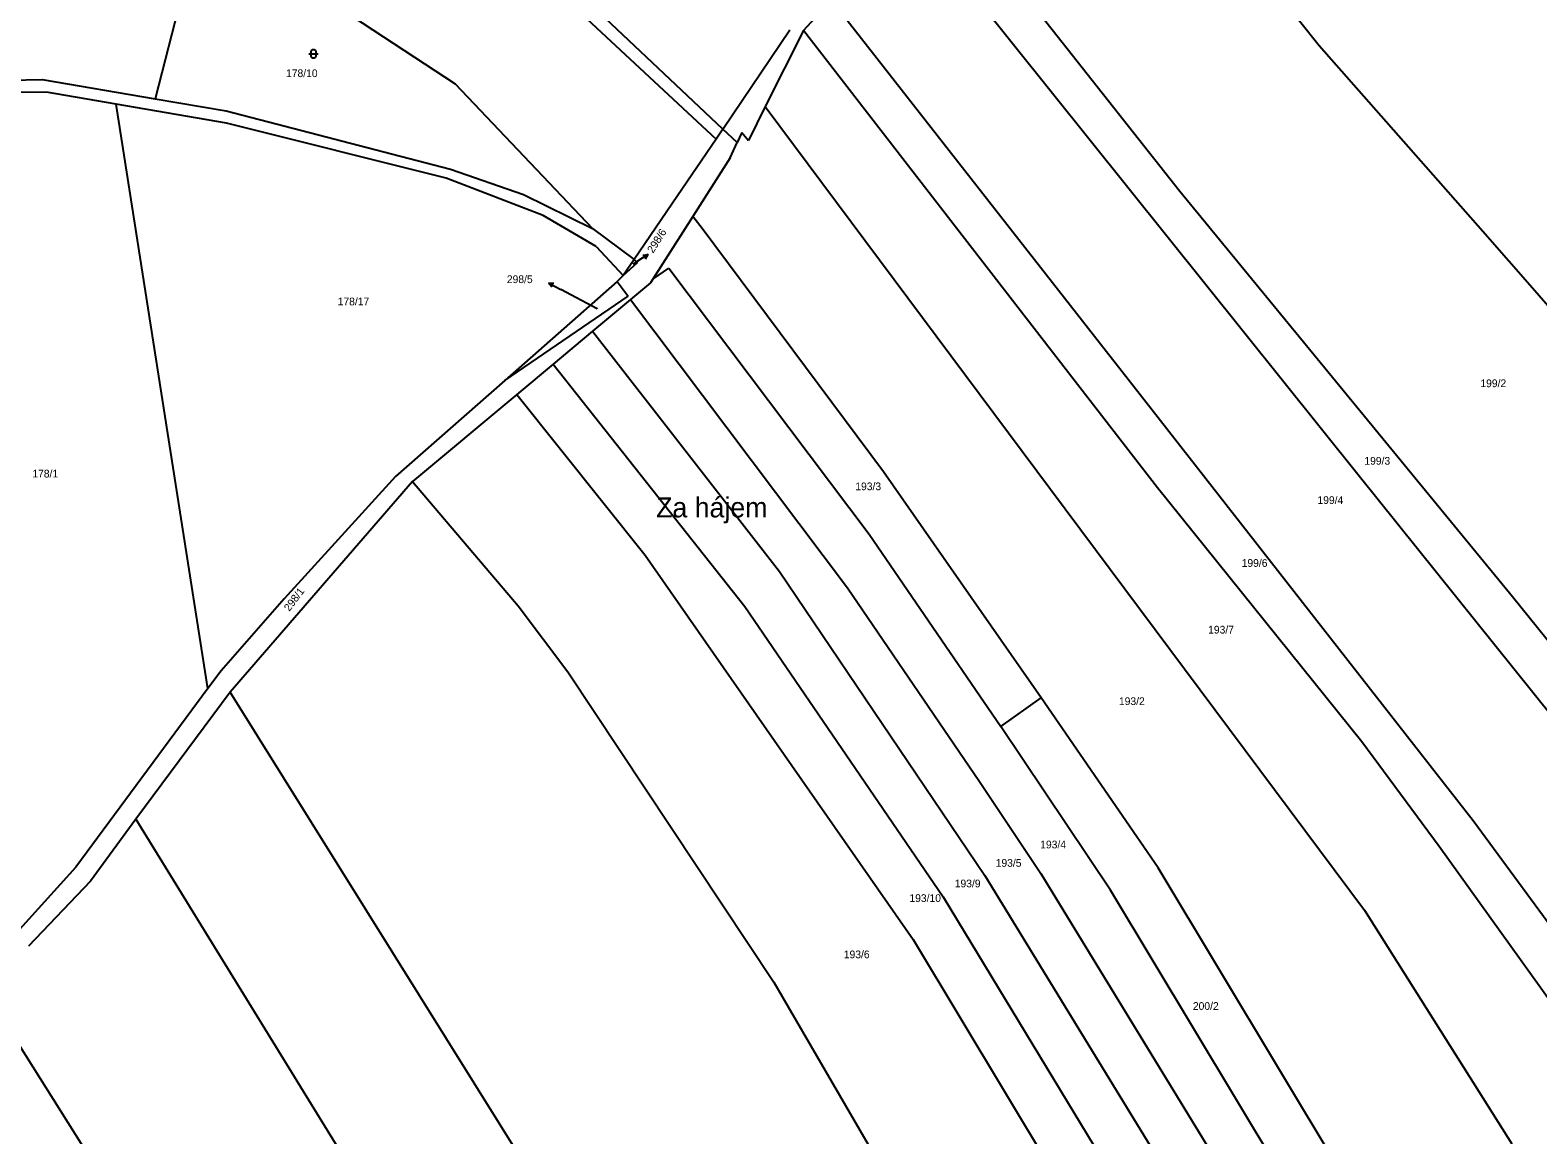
# Model space of a CAD drawing. Extents: x -779723 to -777378, y -1011169 to -1009297.
# Drawn here: x -779291.4 to -778959.2, y -1010989 to -1010745.7 of the extents above; entities that cross this region are included whole.
import ezdxf

# ---------------------------------------------------------------- set-up
doc = ezdxf.new("R2010")
doc.units = 0
for name, color, linetype in [('Default', 7, 'Continuous'), ('KN_HRANICE', 7, 'Continuous'), ('KN_KULTURY', 7, 'Continuous'), ('KN_PARCELY', 7, 'Continuous')]:
    doc.layers.add(name, color=color, linetype=linetype)

# ---------------------------------------------------------------- blocks, each defined once
blk = doc.blocks.new('316')
at = {"layer": 'Default'}
for points in [[(-1, 1), (0.27, 1), (1, 1)], [(-0.5, 1.5), (-0.4, 1.79), (-0.15, 1.97), (0.16, 1.97), (0.41, 1.79), (0.51, 1.5), (0.51, 0.5), (0.41, 0.21), (0.16, 0.03), (-0.15, 0.03), (-0.4, 0.21), (-0.5, 0.5), (-0.5, 1.5)]]:
    blk.add_lwpolyline(points, dxfattribs=at)
blk = doc.blocks.new('10292')
at = {"layer": 'Default'}
blk.add_line((0, 3), (0, 0), dxfattribs=at)
blk.add_lwpolyline([(-0.5, 2), (0, 3), (0.5, 2)], dxfattribs=at)

msp = doc.modelspace()

# ---------------------------------------------------------------- linework, layer by layer
at = {"layer": 'KN_HRANICE'}
for p, q in [((-779090.15, -1010715.21), (-779038.14, -1010781.12)), ((-779034.27, -1010715.3), (-779007.39, -1010749.08)), ((-778998.61, -1010843.93), (-779096.96, -1010721.21)), ((-779246.07, -1010725.76), (-779197.77, -1010757.47)), ((-779255.21, -1010727.12), (-779263.87, -1010760.8)), ((-779138.78, -1010767.46), (-779171.89, -1010736.2)), ((-779174.03, -1010738.22), (-779140.28, -1010769.67)), ((-779121, -1010745.73), (-779114.85, -1010739.08)), ((-779114.85, -1010739.08), (-779044.24, -1010829.34)), ((-779138.78, -1010767.46), (-779124.03, -1010745.63)), ((-779121, -1010745.73), (-779129.44, -1010762.47)), ((-779043.05, -1010846.46), (-779121, -1010745.73)), ((-779007.39, -1010749.08), (-778971.37, -1010789.97)), ((-779295.87, -1010756.68), (-779288.73, -1010756.56)), ((-779287.82, -1010759.31), (-779295.7, -1010759.39)), ((-779288.73, -1010756.56), (-779263.87, -1010760.8)), ((-779272.43, -1010762.01), (-779287.82, -1010759.31)), ((-779197.77, -1010757.47), (-779167.5, -1010789.36)), ((-779252.21, -1010890.71), (-779272.43, -1010762.01)), ((-779248.15, -1010766.16), (-779272.43, -1010762.01)), ((-779263.87, -1010760.8), (-779248.18, -1010763.48)), ((-779129.44, -1010762.47), (-779133.14, -1010770)), ((-779129.44, -1010762.47), (-779063.39, -1010851.12)), ((-779248.18, -1010763.48), (-779198.78, -1010776.27)), ((-779199.71, -1010778.27), (-779248.15, -1010766.16)), ((-779138.78, -1010767.46), (-779140.28, -1010769.67)), ((-779135.61, -1010770.46), (-779138.78, -1010767.46)), ((-779134.58, -1010768.25), (-779135.61, -1010770.46)), ((-779134.58, -1010768.25), (-779133.14, -1010770)), ((-779140.28, -1010769.67), (-779148.79, -1010782.17)), ((-779137.14, -1010773.83), (-779135.61, -1010770.46)), ((-779137.14, -1010773.83), (-779143.83, -1010784.29)), ((-779178.37, -1010786.48), (-779199.71, -1010778.27)), ((-779198.78, -1010776.27), (-779182.71, -1010781.86)), ((-779182.71, -1010781.86), (-779167.5, -1010789.36)), ((-779148.79, -1010782.17), (-779158.36, -1010796.23)), ((-779038.14, -1010781.12), (-778964.83, -1010870.44)), ((-779143.83, -1010784.29), (-779145.37, -1010786.69)), ((-779166.68, -1010793.33), (-779178.37, -1010786.48)), ((-779167.5, -1010789.36), (-779158.36, -1010796.23)), ((-779145.37, -1010786.69), (-779154.19, -1010800.5)), ((-779143.35, -1010789.4), (-779145.37, -1010786.69)), ((-779103.43, -1010842.99), (-779143.35, -1010789.4)), ((-778971.37, -1010789.97), (-778959.93, -1010803)), ((-779166.68, -1010793.33), (-779160.74, -1010799.73)), ((-779158.36, -1010796.23), (-779160.74, -1010799.73)), ((-779160.74, -1010799.73), (-779157.56, -1010796.83)), ((-779158.36, -1010796.23), (-779157.56, -1010796.83)), ((-779154.19, -1010800.5), (-779150.71, -1010798.11)), ((-779150.71, -1010798.11), (-779106.53, -1010856.72)), ((-779162.08, -1010801.02), (-779186.85, -1010822.84)), ((-779162.08, -1010801.02), (-779160.74, -1010799.73)), ((-779162.08, -1010801.02), (-779159.66, -1010804.24)), ((-779154.73, -1010801.34), (-779159.1, -1010804.99)), ((-779154.19, -1010800.5), (-779154.73, -1010801.34)), ((-779186.85, -1010822.84), (-779159.66, -1010804.24)), ((-779159.1, -1010804.99), (-779167.52, -1010812.01)), ((-779159.1, -1010804.99), (-779111.3, -1010868.53)), ((-778959.93, -1010803), (-778909.95, -1010860.69)), ((-779167.52, -1010812.01), (-779176.17, -1010819.22)), ((-779167.52, -1010812.01), (-779126.3, -1010864.94)), ((-779176.17, -1010819.22), (-779184.17, -1010825.9)), ((-779176.17, -1010819.22), (-779133.97, -1010872.59)), ((-779186.85, -1010822.84), (-779210.91, -1010844.02)), ((-779184.17, -1010825.9), (-779207.15, -1010845.06)), ((-779184.17, -1010825.9), (-779155.93, -1010861.31)), ((-779044.24, -1010829.34), (-778973.49, -1010919.73)), ((-779207.15, -1010845.06), (-779247.3, -1010891.46)), ((-779210.91, -1010844.02), (-779235.44, -1010870.94)), ((-779207.15, -1010845.06), (-779183.86, -1010872.45)), ((-779068.64, -1010892.72), (-779103.43, -1010842.99)), ((-778900.11, -1010966.64), (-778998.61, -1010843.93)), ((-778998.02, -1010902.45), (-779043.05, -1010846.46)), ((-779063.39, -1010851.12), (-778997.44, -1010939.52)), ((-779106.53, -1010856.72), (-779077.58, -1010899.08)), ((-779155.93, -1010861.31), (-779096.86, -1010945.95)), ((-779126.3, -1010864.94), (-779081.05, -1010931.89)), ((-779111.3, -1010868.53), (-779082.24, -1010911.14)), ((-779235.44, -1010870.94), (-779249.3, -1010886.77)), ((-778964.83, -1010870.44), (-778892.41, -1010960.42)), ((-779183.86, -1010872.45), (-779172.91, -1010886.98)), ((-779133.97, -1010872.59), (-779090.28, -1010936.59)), ((-779249.3, -1010886.77), (-779252.21, -1010890.71)), ((-779172.91, -1010886.98), (-779127.56, -1010955.39)), ((-779252.21, -1010890.71), (-779281.31, -1010930.07)), ((-779247.3, -1010891.46), (-779268.1, -1010919.48)), ((-779161.56, -1011028.82), (-779247.3, -1010891.46)), ((-779077.58, -1010899.08), (-779068.64, -1010892.72)), ((-779042.92, -1010930.15), (-779068.64, -1010892.72)), ((-779053.4, -1010935.08), (-779077.58, -1010899.08)), ((-778980.97, -1010925.46), (-778998.02, -1010902.45)), ((-779082.24, -1010911.14), (-779068.7, -1010931.41)), ((-779268.1, -1010919.48), (-779278.06, -1010933.1)), ((-779268.1, -1010919.48), (-779212.73, -1011009.48)), ((-778973.49, -1010919.73), (-778924.2, -1010986.99)), ((-778944.73, -1010976.05), (-778980.97, -1010925.46)), ((-779281.31, -1010930.07), (-779295.1, -1010945.28)), ((-779081.05, -1010931.89), (-779020.18, -1011031.25)), ((-779068.7, -1010931.41), (-779011.43, -1011025.21)), ((-778993.64, -1011012.17), (-779042.92, -1010930.15)), ((-779278.06, -1010933.1), (-779291.76, -1010947.43)), ((-779002.79, -1011019.26), (-779053.4, -1010935.08)), ((-779090.28, -1010936.59), (-779029.06, -1011037.37)), ((-778997.44, -1010939.52), (-778964.98, -1010991)), ((-779096.86, -1010945.95), (-779038.09, -1011043.59)), ((-779127.56, -1010955.39), (-779091.73, -1011017)), ((-779300.33, -1010958.9), (-779206.63, -1011107.76))]:
    msp.add_line(p, q, dxfattribs=at)
at = {"layer": 'KN_PARCELY'}
for p, q in [((-779158.56, -1010797.19), (-779157.83, -1010796.73)), ((-779166.51, -1010807.07), (-779174.48, -1010802.81))]:
    msp.add_line(p, q, dxfattribs=at)

# ---------------------------------------------------------------- block references
at = {"layer": 'KN_KULTURY'}
msp.add_blockref('316', (-779228.96, -1010751.91), dxfattribs=at)
at = {"layer": 'KN_PARCELY'}
for p, rotation in [((-779157.83, -1010796.73), -57.70746700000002), ((-779174.48, -1010802.81), 61.822146)]:
    msp.add_blockref('10292', p, dxfattribs=dict(at, rotation=rotation))

# ---------------------------------------------------------------- texts
for s, height, p in [('178/10', 1.7, (-779235.02, -1010756.02)), ('298/5', 1.7, (-779186.37, -1010801.39)), ('178/17', 1.7, (-779223.64, -1010806.29)), ('298/5', 0.1, (-779166.5, -1010807.07)), ('199/2', 1.7, (-778971.9, -1010824.31)), ('178/1', 1.7, (-779290.91, -1010844.21)), ('199/3', 1.7, (-778997.46, -1010841.39)), ('193/3', 1.7, (-779109.61, -1010847.01)), ('Za hájem', 4.4, (-779153.49, -1010853)), ('199/4', 1.7, (-779007.79, -1010850.04)), ('199/6', 1.7, (-779024.49, -1010863.89)), ('193/7', 1.7, (-779031.88, -1010878.58)), ('193/2', 1.7, (-779051.53, -1010894.33)), ('193/4', 1.7, (-779068.87, -1010925.9)), ('193/5', 1.7, (-779078.68, -1010929.95)), ('193/9', 1.7, (-779087.7, -1010934.48)), ('193/10', 1.7, (-779097.69, -1010937.7)), ('193/6', 1.7, (-779112.14, -1010950.1)), ('200/2', 1.7, (-779035.24, -1010961.47))]:
    msp.add_text(s, height=height, dxfattribs=at).set_placement(p)
for s, height, rotation, p in [('298/6', 1.7, 57.64, (-779154.16, -1010794.93)), ('298/6', 0.1, 57.124, (-779158.56, -1010797.18)), ('298/1', 1.7, 53.113, (-779234.28, -1010873.83))]:
    msp.add_text(s, height=height, rotation=rotation, dxfattribs=at).set_placement(p)

doc.saveas('drawing.dxf')
